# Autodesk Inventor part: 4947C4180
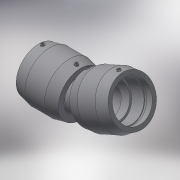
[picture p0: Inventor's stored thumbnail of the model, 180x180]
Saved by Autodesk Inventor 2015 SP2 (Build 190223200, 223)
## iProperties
Created: 2017-06
Part Number: 4947C4180
Material: Generic
Description: PLASSON ADJUSTABLE ELBOW 180
Document SubType Name: Modeling
Designer: KIM
Mass: 6776.68 g
Surface Area: 6960.85 cm^2
Volume: 6776.68 cm^3
Density: 1 g/cm^3
Appearance: Default
Author: KIM
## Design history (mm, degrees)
derived "4947C4.ipt"
feature "Solid1::4947C4.ipt"
tag "TaggingFeature1"
body "Solid1"
other parameters: "d0" = 204.4, "d2" = 224, "d3" = 104, "d4" = 52, "d5" = 201.6, "d8" = 168 deg, "d10" = 41.6, "d11" = 13.86667, "d29" = 128, "d30" = 15, "d31" = 81.76, "d34" = 5 deg, "d41" = 4, "d42" = 14, "d43" = 0, "d48" = 162, "d49" = 24 deg, "d50" = 511, "d51" = 78 deg, "d52" = 90 deg, "d55" = 50.2, "d57" = 168 deg, "d58" = 10.04, "d60" = 60.33179, "d62" = 3, "d63" = 0, "L_" = 511, "L_1" = 104, "D_" = 224, "A_" = 128, "d_2" = 12, "L_0" = 148, "d54" = 100.4, "d59" = 201.10598
